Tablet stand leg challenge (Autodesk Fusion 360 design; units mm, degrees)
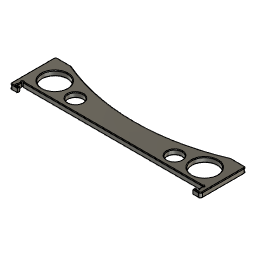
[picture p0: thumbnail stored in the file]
sketch "Sketch1" plane through (0, 0, 0) normal (0, 0, 1) x axis (1, 0, 0)
  line L1 (238.125, 0) -> (0, 0)
  line L2 (238.125, 57.15) -> (238.125, 0)
  line L3 (0, 57.15) -> (238.125, 57.15)
  line L4 (0, 0) -> (0, 57.15)
  point P1 (0, 0)
  point P2 (0, 0)
  point P3 (238.125, 0)
  point P5 (0, 57.15)
  horizontal L1
  vertical L2
  horizontal L3
  vertical L4
  coincident P1 P2
  dimension "d1" distance P2 P3 = 238.125
  dimension "d2" distance P2 P5 = 57.15
extrude "Extrude1" new body sketch "Sketch1" along normal blind 6.35
sketch "Sketch2" plane through (0, 0, 6.35) normal (0, 0, 1) x axis (-1, 0, 0)
  line L1 (0, 0) -> (0, -57.15)
  line L2 (-238.125, 0) -> (0, 0)
  line L3 (-238.125, -57.15) -> (-238.125, 0)
  line L4 (0, -57.15) -> (-238.125, -57.15)
  line L5 (-19.05, -57.15) -> (0, -57.15)
  line L6 (-219.075, -57.15) -> (-238.125, -57.15)
  line L7 (-219.075, -57.15) -> (-19.05, -57.15)
  line L8 (-231.902, 0) -> (-6.223, 0)
  line L9 (-231.902, -9.525) -> (-231.902, 0)
  line L10 (-6.223, -9.525) -> (-231.902, -9.525)
  line L11 (-6.223, 0) -> (-6.223, -9.525)
  line L12 (-228.727, 0) -> (-231.902, 0)
  line L13 (-228.727, -3.048) -> (-228.727, 0)
  line L14 (-231.902, -3.048) -> (-228.727, -3.048)
  line L15 (-231.902, 0) -> (-231.902, -3.048)
  line L16 (-9.398, 0) -> (-6.223, 0)
  line L17 (-9.398, -3.048) -> (-9.398, 0)
  line L18 (-6.223, -3.048) -> (-9.398, -3.048)
  line L19 (-6.223, 0) -> (-6.223, -3.048)
  arc A1 centre (-119.0625, -290.6313) radius 254 clockwise from (-219.075, -57.15) to (-19.05, -57.15)
  point P2 (0, -57.15)
  point P6 (0, -57.15)
  point P5 (-238.125, -57.15)
  point P8 (-238.125, -57.15)
  point P11 (-6.223, 0)
  point P7 (-19.05, -57.15)
  point P9 (-219.075, -57.15)
  point P12 (-231.902, 0)
  point P15 (-228.727, 0)
  point P17 (-231.902, -3.048)
  point P18 (-9.398, 0)
  point P20 (-6.223, -3.048)
  coincident P2 P6
  perpendicular L1 L5
  coincident P5 P8
  perpendicular L3 L6
  horizontal L8
  vertical L9
  horizontal L10
  vertical L11
  coincident L2 P11
  horizontal L12
  vertical L13
  horizontal L14
  vertical L15
  horizontal L16
  vertical L17
  horizontal L18
  vertical L19
  dimension "d5" distance P6 P7 = 19.05
  dimension "d6" distance P8 P9 = 19.05
  dimension "d7" radius A1 = 254
  dimension "d8" distance L8 L10 = 9.525
  dimension "d9" distance L9 L11 = 225.679
  dimension "d10" distance L3 L9 = 6.223
  dimension "d11" distance P12 P15 = 3.175
  dimension "d12" distance P12 P17 = 3.048
  dimension "d13" distance P11 P18 = 3.175
  dimension "d14" distance P11 P20 = 3.048
extrude "Extrude2" cut sketch "Sketch2" profile of L2 L4 A1 L7 L8 L9 L10 L11 L13 L14 L17 L18 no distance stored
sketch "Sketch3" plane through (0, 0, 6.35) normal (0, 0, 1) x axis (-1, 0, 0)
  line L1 (-231.902, -9.525) -> (-6.223, -9.525)
  line L2 (-231.902, -3.048) -> (-231.902, -9.525)
  line L3 (-228.727, -3.048) -> (-231.902, -3.048)
  line L4 (-228.727, 0) -> (-228.727, -3.048)
  line L5 (-238.125, 0) -> (-228.727, 0)
  line L6 (-238.125, -57.15) -> (-238.125, 0)
  line L7 (-219.075, -57.15) -> (-238.125, -57.15)
  line L8 (0, -57.15) -> (-19.05, -57.15)
  line L9 (0, 0) -> (0, -57.15)
  line L10 (-9.398, 0) -> (0, 0)
  line L11 (-9.398, -3.048) -> (-9.398, 0)
  line L12 (-6.223, -3.048) -> (-9.398, -3.048)
  line L13 (-6.223, -9.525) -> (-6.223, -3.048)
  arc A1 centre (-119.0625, -290.6313) radius 254 clockwise from (-219.075, -57.15) to (-19.05, -57.15)
  circle C1 centre (-25.4, -30.734) radius 15.875
  circle C2 centre (-57.15, -24.765) radius 9.3345
  point P18 (-25.4, -30.734)
  point P19 (-57.15, -24.765)
  dimension "d19" distance L9 P18 = 25.4
  dimension "d20" distance L9 P19 = 57.15
  dimension "d21" diameter C2 = 18.669
  dimension "d22" diameter C1 = 31.75
  dimension "d23" distance L1 P19 = 15.24
  dimension "d24" distance L1 P18 = 21.209
extrude "Extrude3" cut sketch "Sketch3" profile of C1 C2 no distance stored
work_plane "WorkPlane1"
mirror "Mirror1" mirrorStitchTolerance 0.1016
hole "Hole2" HoleDepth 6.35 HoleDiameter 2.032 TipAngle 118
hole "Hole3" HoleDepth 6.35 HoleDiameter 2.032 TipAngle 118
hole "Hole4" HoleDepth 6.35 HoleDiameter 2.032 TipAngle 118
hole "Hole5" HoleDepth 6.35 HoleDiameter 2.032 TipAngle 118
fillet "Fillet1" radius 2.54
chamfer "Chamfer1" distance 0.762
